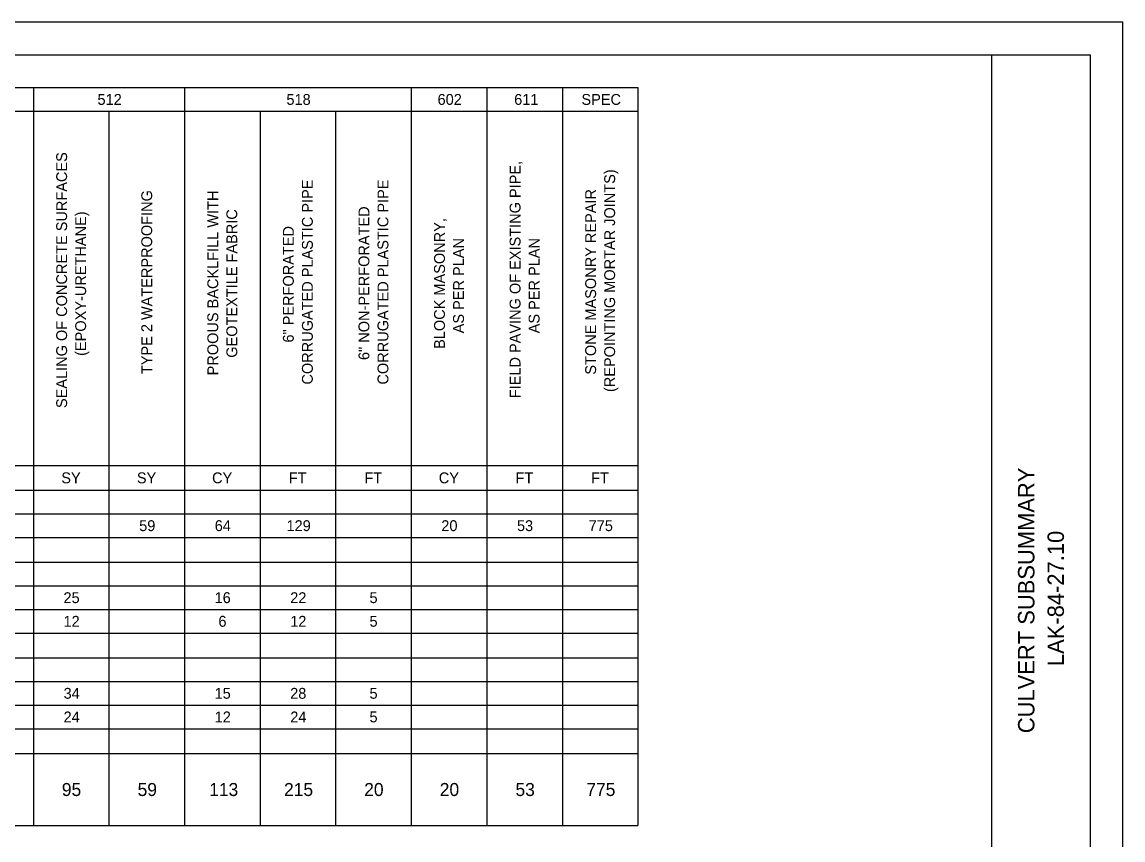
# Model space of a CAD drawing. Extents: x 0 to 34, y -1.2 to 22.
# Drawn here: x 17.22 to 34, y 9.53 to 22 of the extents above; entities that cross this region are included whole.
import ezdxf

# ---------------------------------------------------------------- set-up
doc = ezdxf.new("R2010")
doc.units = 0
for name, color, linetype in [('SH_Border', 7, 'Continuous'), ('SH_Cut_Line', 7, 'Continuous'), ('SH_Data', 7, 'Continuous'), ('SH_Text', 7, 'Continuous')]:
    doc.layers.add(name, color=color, linetype=linetype)

msp = doc.modelspace()

# ---------------------------------------------------------------- linework, layer by layer
at = {"layer": 'SH_Border'}
msp.add_line((32, 0.5), (32, 21.5), dxfattribs=at)
msp.add_lwpolyline([(1.5, 21.5), (33.5, 21.5), (33.5, 0.5), (1.5, 0.5)], close=True, dxfattribs=at)
at = {"layer": 'SH_Cut_Line'}
msp.add_lwpolyline([(0, 0), (34, 0), (34, 22), (0, 22)], close=True, dxfattribs=at)
at = {"layer": 'SH_Text'}
for p, q in [((2, 21), (26.606, 21)), ((17.39, 21), (17.39, 9.75)), ((19.694, 21), (19.694, 9.75)), ((23.15, 21), (23.15, 9.75)), ((24.302, 21), (24.302, 9.75)), ((25.454, 21), (25.454, 9.75)), ((26.606, 21), (26.606, 9.75)), ((7.022, 20.64), (26.606, 20.64)), ((18.542, 20.64), (18.542, 9.75)), ((20.846, 20.64), (20.846, 9.75)), ((21.998, 20.64), (21.998, 9.75)), ((7.022, 15.24), (26.606, 15.24)), ((2, 14.862), (26.606, 14.862)), ((2, 14.502), (26.606, 14.502)), ((2, 14.142), (26.606, 14.142)), ((2, 13.764), (26.606, 13.764)), ((2, 13.404), (26.606, 13.404)), ((2, 13.044), (26.606, 13.044)), ((2, 12.684), (26.606, 12.684)), ((2, 12.306), (26.606, 12.306)), ((2, 11.946), (26.606, 11.946)), ((2, 11.586), (26.606, 11.586)), ((2, 11.226), (26.606, 11.226)), ((2, 10.848), (26.606, 10.848)), ((2, 9.75), (26.606, 9.75))]:
    msp.add_line(p, q, dxfattribs=at)

# ---------------------------------------------------------------- texts
at = {"layer": 'SH_Data'}
for s, p in [('CULVERT SUBSUMMARY', (32.65, 11.158)), ('LAK-84-27.10', (33.1, 12.181))]:
    msp.add_text(s, height=0.25, rotation=90, dxfattribs=at).set_placement(p)
at = {"layer": 'SH_Text'}
for s, height, p in [('512', 0.1656, (18.368, 20.737)), ('518', 0.1656, (21.248, 20.737)), ('602', 0.1656, (23.552, 20.737)), ('611', 0.1656, (24.72, 20.737)), ('SPEC', 0.1656, (25.745, 20.737)), ('SY', 0.1656, (17.816, 14.968)), ('SY', 0.1656, (18.968, 14.968)), ('CY', 0.1656, (20.114, 14.968)), ('FT', 0.1656, (21.284, 14.968)), ('FT', 0.1656, (22.436, 14.968)), ('CY', 0.1656, (23.57, 14.968)), ('FT', 0.1656, (24.74, 14.968)), ('FT', 0.1656, (25.892, 14.968)), ('59', 0.1656, (19.003, 14.239)), ('64', 0.1656, (20.155, 14.239)), ('129', 0.1656, (21.249, 14.239)), ('20', 0.1656, (23.609, 14.239)), ('53', 0.1656, (24.762, 14.239)), ('775', 0.1656, (25.855, 14.239)), ('25', 0.1656, (17.849, 13.141)), ('16', 0.1656, (20.153, 13.141)), ('22', 0.1656, (21.306, 13.141)), ('5', 0.166, (22.514, 13.141)), ('12', 0.1656, (17.85, 12.781)), ('6', 0.166, (20.211, 12.781)), ('12', 0.1656, (21.306, 12.781)), ('5', 0.166, (22.514, 12.781)), ('34', 0.1656, (17.851, 11.683)), ('15', 0.1656, (20.153, 11.683)), ('28', 0.1656, (21.305, 11.683)), ('5', 0.166, (22.514, 11.683)), ('24', 0.1656, (17.851, 11.323)), ('12', 0.1656, (20.154, 11.323)), ('24', 0.1656, (21.307, 11.323)), ('5', 0.166, (22.514, 11.323)), ('95', 0.1987, (17.824, 10.2)), ('59', 0.1987, (18.979, 10.2)), ('113', 0.1987, (20.07, 10.2)), ('215', 0.1987, (21.211, 10.2)), ('20', 0.1987, (22.433, 10.2)), ('20', 0.1987, (23.585, 10.2)), ('53', 0.1987, (24.739, 10.2)), ('775', 0.1987, (25.819, 10.2))]:
    msp.add_text(s, height=height, dxfattribs=at).set_placement(p)
for s, p in [('SEALING OF CONCRETE SURFACES', (17.904, 16.115)), ('FIELD PAVING OF EXISTING PIPE,', (24.816, 16.265)), ('(REPOINTING MORTAR JOINTS)', (26.258, 16.359)), ('CORRUGATED PLASTIC PIPE', (21.65, 16.473)), ('CORRUGATED PLASTIC PIPE', (22.802, 16.473)), ('TYPE 2 WATERPROOFING', (19.201, 16.632)), ('PROOUS BACKLFILL WITH', (20.208, 16.613)), ('STONE MASONRY REPAIR', (25.968, 16.624)), ('GEOTEXTILE FABRIC', (20.498, 16.882)), ('6" NON-PERFORATED', (22.512, 16.847)), ('(EPOXY-URETHANE)', (18.194, 16.91)), ('BLOCK MASONRY,', (23.664, 17.017)), ('6" PERFORATED', (21.36, 17.113)), ('AS PER PLAN', (23.954, 17.254)), ('AS PER PLAN', (25.106, 17.254))]:
    msp.add_text(s, height=0.1656, rotation=90, dxfattribs=at).set_placement(p)

doc.saveas('drawing.dxf')
